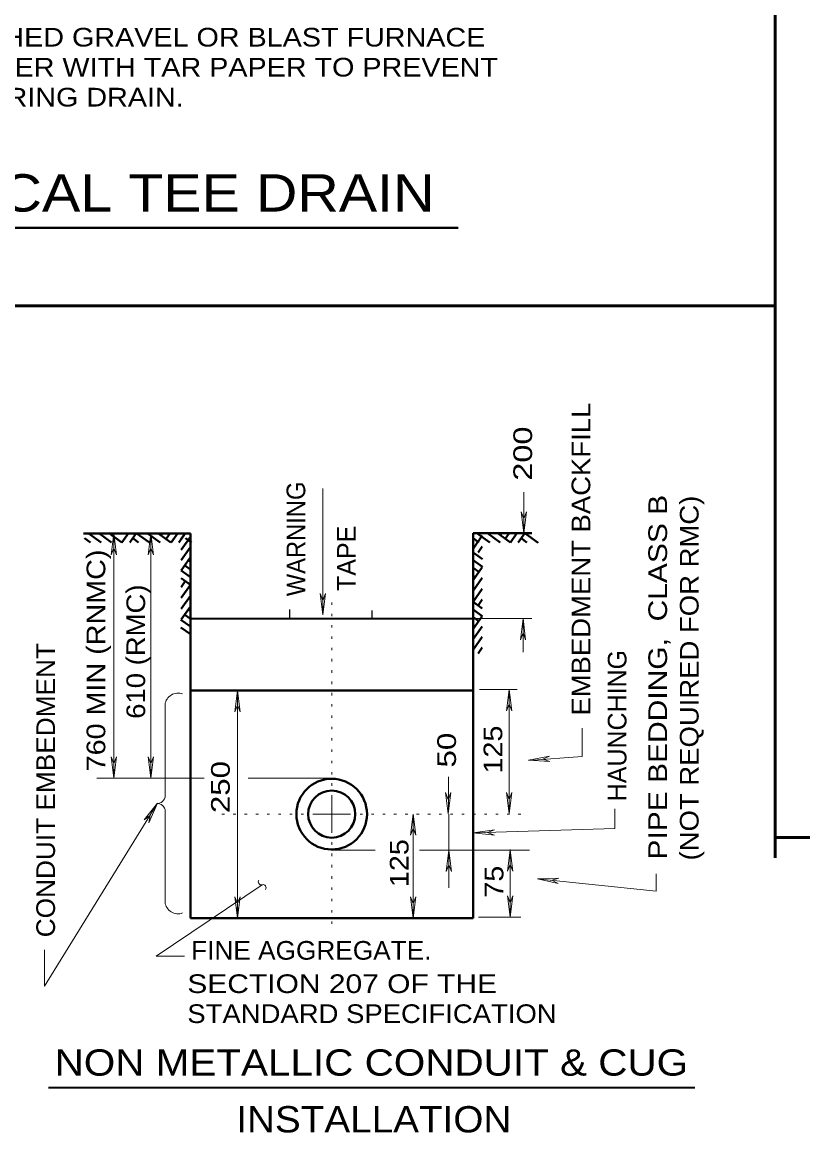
# Model space of a CAD drawing. Extents: x 312583 to 312854, y 144419 to 144597.
# Drawn here: x 312765.96 to 312797.73, y 144444.15 to 144489.34 of the extents above; entities that cross this region are included whole.
import ezdxf
from ezdxf.enums import TextEntityAlignment as Align

# ---------------------------------------------------------------- set-up
doc = ezdxf.new("R2010")
doc.units = 0
doc.header["$LTSCALE"] = 0.3
doc.linetypes.add('DOTTED', pattern=[1.5, 0.3, -1.2])
doc.layers.add('1', color=7, linetype='Continuous', lineweight=40)
doc.layers.add('2', color=7, linetype='Continuous', lineweight=13)

msp = doc.modelspace()

# ---------------------------------------------------------------- linework, layer by layer
at = {"layer": '1', "lineweight": 53}
for p, q in [((312796.6103, 144455.3281), (312796.6103, 144540.9979)), ((312796.6103, 144477.7945), (312742.1369, 144477.7945)), ((312849, 144456.1666), (312796.6103, 144456.1666))]:
    msp.add_line(p, q, dxfattribs=at)
at = {"layer": '1'}
for p, q in [((312772.8133, 144468.5326), (312768.4509, 144468.5326)), ((312769.1793, 144468.1646), (312768.6503, 144468.5479)), ((312769.6009, 144468.1646), (312769.0796, 144468.5402)), ((312770.0226, 144468.1646), (312769.4783, 144468.5556)), ((312769.6623, 144468.5479), (312769.6009, 144468.4636)), ((312770.2909, 144468.5479), (312770.0226, 144468.1646)), ((312770.6053, 144468.5479), (312770.3369, 144468.1646)), ((312771.1419, 144468.1646), (312770.6053, 144468.5479)), ((312771.5789, 144468.1646), (312771.0423, 144468.5479)), ((312772.0159, 144468.1646), (312771.4869, 144468.5479)), ((312771.6709, 144468.5402), (312771.6096, 144468.4559)), ((312771.9853, 144468.5402), (312771.8166, 144468.3102)), ((312772.2996, 144468.5402), (312772.0313, 144468.1646)), ((312772.6139, 144468.5402), (312772.3379, 144468.1646)), ((312772.8133, 144452.8849), (312772.8133, 144468.5326)), ((312784.3133, 144463.6489), (312784.3133, 144468.5479)), ((312784.3133, 144468.5479), (312786.7053, 144468.5479)), ((312784.9956, 144468.1646), (312784.4589, 144468.5479)), ((312785.4173, 144468.1646), (312784.8959, 144468.5402)), ((312785.8313, 144468.1646), (312785.2869, 144468.5556)), ((312785.4709, 144468.5479), (312785.4096, 144468.4636)), ((312785.7853, 144468.5479), (312785.6243, 144468.3179)), ((312786.0996, 144468.5479), (312785.8313, 144468.1646)), ((312786.4139, 144468.5479), (312786.1456, 144468.1646)), ((312786.9583, 144468.1569), (312786.4216, 144468.5402)), ((312768.7423, 144468.1646), (312768.4969, 144468.3409)), ((312770.6973, 144468.1646), (312770.4596, 144468.3409)), ((312772.8516, 144468.1646), (312772.6139, 144468.3409)), ((312784.5509, 144468.1646), (312784.3133, 144468.3409)), ((312786.5059, 144468.1646), (312786.2683, 144468.3409)), ((312778.5556, 144458.5506), (312778.5173, 144458.5506))]:
    msp.add_line(p, q, dxfattribs=at)
at = {"layer": '1', "lineweight": 13}
for p, q in [((312771.7783, 144461.5712), (312771.7783, 144457.9372)), ((312773.3653, 144458.5812), (312768.9953, 144458.5812)), ((312778.5556, 144458.5812), (312775.1593, 144458.5812)), ((312771.7783, 144453.5212), (312771.7783, 144457.1629))]:
    msp.add_line(p, q, dxfattribs=at)
for centre, radius, start, end in [((312772.3085, 144461.4991), 0.5391, 70.18032, 172.10697), ((312771.4615, 144457.8674), 0.3202, 274.55734, 12.2494), ((312771.4615, 144457.2289), 0.3202, 347.7506, 85.44266), ((312772.3085, 144453.5972), 0.5391, 187.89303, 289.81968)]:
    msp.add_arc(centre, radius, start, end, dxfattribs=at)
at = {"layer": '2', "lineweight": 40}
for p, q in [((312759.9676, 144480.9679), (312783.709, 144480.9679)), ((312772.4299, 144468.3102), (312772.5986, 144468.5479)), ((312772.4299, 144467.8656), (312772.8133, 144468.4022)), ((312784.6889, 144468.4482), (312784.3133, 144467.9116)), ((312772.4299, 144467.4439), (312772.7979, 144467.9652)), ((312784.6889, 144468.0036), (312784.5203, 144467.7659)), ((312772.4299, 144467.0299), (312772.8133, 144467.5742)), ((312784.3133, 144467.7659), (312784.6966, 144467.4899)), ((312772.8133, 144466.7616), (312772.4299, 144467.0299)), ((312772.8133, 144467.0682), (312772.5756, 144467.2369)), ((312772.8133, 144467.3826), (312772.7289, 144467.4439)), ((312784.3133, 144467.4516), (312784.6966, 144467.1756)), ((312784.6889, 144467.1679), (312784.3133, 144466.6312)), ((312784.3133, 144467.1372), (312784.5509, 144466.9686)), ((312772.8133, 144466.4472), (312772.4299, 144466.7156)), ((312772.4299, 144466.3476), (312772.5986, 144466.5929)), ((312784.3133, 144466.8229), (312784.3976, 144466.7616)), ((312784.6889, 144466.7309), (312784.3133, 144466.1942)), ((312772.4299, 144465.9106), (312772.8133, 144466.4472)), ((312784.6889, 144466.2862), (312784.3133, 144465.7572)), ((312772.4299, 144465.4736), (312772.8133, 144466.0026)), ((312784.3133, 144465.7572), (312784.6889, 144465.4812)), ((312784.6889, 144465.8492), (312784.5203, 144465.6039)), ((312772.4299, 144465.0289), (312772.8133, 144465.5656)), ((312772.8056, 144465.0596), (312772.5756, 144465.2282)), ((312772.8056, 144465.3739), (312772.7213, 144465.4352)), ((312784.3133, 144465.4429), (312784.6889, 144465.1669)), ((312772.8056, 144464.7529), (312772.4223, 144465.0212)), ((312784.6889, 144465.1669), (312784.3056, 144464.6226)), ((312784.3133, 144465.1286), (312784.5433, 144464.9599)), ((312784.3133, 144464.8142), (312784.3976, 144464.7529)), ((312772.8056, 144464.4386), (312772.4223, 144464.7069)), ((312784.6889, 144464.3312), (312784.3133, 144463.7946)), ((312784.6889, 144464.7529), (312784.3209, 144464.2316)), ((312784.6889, 144463.8942), (312784.5203, 144463.6489)), ((312784.3133, 144463.6489), (312784.3133, 144452.8849)), ((312772.8133, 144462.1386), (312784.3133, 144462.1386)), ((312772.8133, 144452.8849), (312784.3133, 144452.8849))]:
    msp.add_line(p, q, dxfattribs=at)
at = {"layer": '2'}
for p, q in [((312778.1953, 144470.3649), (312778.1953, 144465.2206)), ((312786.3833, 144468.5862), (312786.3833, 144470.2192)), ((312786.2759, 144469.4142), (312786.3833, 144469.1382)), ((312786.3833, 144468.5479), (312786.2759, 144469.4142)), ((312786.4906, 144469.4142), (312786.3833, 144469.1382)), ((312786.3833, 144468.5479), (312786.4906, 144469.4142)), ((312769.6929, 144468.5326), (312769.5856, 144467.6662)), ((312769.6929, 144468.5326), (312769.6929, 144458.5812)), ((312769.6929, 144468.5326), (312769.8003, 144467.6662)), ((312771.2033, 144468.5326), (312771.0959, 144467.6662)), ((312771.2033, 144468.5326), (312771.3106, 144467.6662)), ((312771.2033, 144468.4329), (312771.2033, 144458.5812)), ((312769.5856, 144467.6662), (312769.6929, 144467.9422)), ((312769.8003, 144467.6662), (312769.6929, 144467.9422)), ((312771.0959, 144467.6662), (312771.2033, 144467.9422)), ((312771.3106, 144467.6662), (312771.2033, 144467.9422)), ((312778.0879, 144466.0869), (312778.1953, 144465.8109)), ((312778.1953, 144465.2206), (312778.0879, 144466.0869)), ((312778.3026, 144466.0869), (312778.1953, 144465.8109)), ((312778.1953, 144465.2206), (312778.3026, 144466.0869)), ((312784.3133, 144465.0749), (312786.7053, 144465.0749)), ((312786.3449, 144465.0749), (312786.2376, 144464.2086)), ((312786.3449, 144465.0749), (312786.4523, 144464.2086)), ((312786.3449, 144463.7102), (312786.3449, 144465.0366)), ((312786.2376, 144464.2086), (312786.3449, 144464.4846)), ((312786.4523, 144464.2086), (312786.3449, 144464.4846)), ((312774.7223, 144462.1386), (312774.6149, 144461.2722)), ((312774.7223, 144462.1386), (312774.7223, 144452.8849)), ((312774.7223, 144462.1386), (312774.8296, 144461.2722)), ((312784.5739, 144462.1846), (312786.1099, 144462.1846)), ((312785.781, 144462.1846), (312785.6736, 144461.3182)), ((312785.781, 144462.1156), (312785.781, 144462.1846)), ((312785.781, 144462.1846), (312785.8883, 144461.3182)), ((312785.781, 144462.1846), (312785.781, 144457.1246)), ((312774.6149, 144461.2722), (312774.7223, 144461.5482)), ((312774.8296, 144461.2722), (312774.7223, 144461.5482)), ((312785.6736, 144461.3182), (312785.781, 144461.5942)), ((312785.8883, 144461.3182), (312785.781, 144461.5942)), ((312788.7523, 144460.6129), (312788.7523, 144459.4629)), ((312769.5856, 144459.4476), (312769.6929, 144459.1716)), ((312769.6929, 144458.5812), (312769.5856, 144459.4476)), ((312769.8003, 144459.4476), (312769.6929, 144459.1716)), ((312769.6929, 144458.5812), (312769.8003, 144459.4476)), ((312771.0959, 144459.4476), (312771.2033, 144459.1716)), ((312771.2033, 144458.5812), (312771.0959, 144459.4476)), ((312771.3106, 144459.4476), (312771.2033, 144459.1716)), ((312771.2033, 144458.5812), (312771.3106, 144459.4476)), ((312786.5673, 144459.3096), (312787.4183, 144459.4706)), ((312788.7523, 144459.4629), (312786.5673, 144459.3019)), ((312787.4183, 144459.4706), (312787.1576, 144459.3479)), ((312787.4413, 144459.2559), (312787.1576, 144459.3479)), ((312786.5673, 144459.3096), (312787.4413, 144459.2559)), ((312783.3089, 144458.6349), (312783.3089, 144457.1936)), ((312783.1939, 144457.9909), (312783.3013, 144457.7149)), ((312783.3013, 144457.1246), (312783.1939, 144457.9909)), ((312783.4086, 144457.9909), (312783.3013, 144457.7149)), ((312783.3013, 144457.1246), (312783.4086, 144457.9909)), ((312785.6736, 144457.9909), (312785.781, 144457.7149)), ((312785.781, 144457.1246), (312785.6736, 144457.9909)), ((312785.8883, 144457.9909), (312785.781, 144457.7149)), ((312785.781, 144457.1246), (312785.8883, 144457.9909)), ((312771.4716, 144457.5616), (312770.9273, 144456.8792)), ((312771.4716, 144457.5616), (312771.1113, 144456.7642)), ((312778.5633, 144457.1169), (312778.5633, 144457.8836)), ((312778.5633, 144457.1169), (312777.7966, 144457.1169)), ((312778.5633, 144457.1169), (312779.3299, 144457.1169)), ((312778.5633, 144457.1169), (312778.5633, 144456.3502)), ((312781.8753, 144457.1169), (312781.7679, 144456.2506)), ((312781.8753, 144457.1169), (312781.8753, 144452.8849)), ((312781.8753, 144457.1169), (312781.9826, 144456.2506)), ((312783.3243, 144457.1092), (312783.3243, 144455.6602)), ((312790.0786, 144457.3239), (312790.0786, 144456.5342)), ((312770.9273, 144456.8792), (312771.1649, 144457.0556)), ((312771.1113, 144456.7642), (312771.1649, 144457.0556)), ((312781.7679, 144456.2506), (312781.8753, 144456.5266)), ((312781.9826, 144456.2506), (312781.8753, 144456.5266)), ((312784.3133, 144456.3579), (312785.1796, 144456.4729)), ((312784.3133, 144456.3579), (312785.1796, 144456.2582)), ((312790.0786, 144456.5342), (312784.3593, 144456.3579)), ((312785.1796, 144456.4729), (312784.9036, 144456.3656)), ((312785.1796, 144456.2582), (312784.9036, 144456.3656)), ((312778.5249, 144455.6526), (312780.3343, 144455.6526)), ((312782.1359, 144455.6526), (312786.606, 144455.6526)), ((312783.3243, 144455.6449), (312783.2169, 144454.7786)), ((312783.3243, 144455.6449), (312783.4316, 144454.7786)), ((312783.3243, 144455.5529), (312783.3243, 144454.1116)), ((312785.8164, 144455.6526), (312785.709, 144454.7862)), ((312785.8164, 144455.6679), (312785.8164, 144452.9156)), ((312785.8164, 144455.6526), (312785.9237, 144454.7862)), ((312783.2169, 144454.7786), (312783.3243, 144455.0546)), ((312783.4316, 144454.7786), (312783.3243, 144455.0546)), ((312785.709, 144454.7862), (312785.8164, 144455.0622)), ((312785.9237, 144454.7862), (312785.8164, 144455.0622)), ((312786.9283, 144454.4865), (312787.8023, 144454.5095)), ((312791.7653, 144453.9812), (312786.9283, 144454.4865)), ((312786.9283, 144454.4865), (312787.7793, 144454.2948)), ((312787.8023, 144454.5095), (312787.5186, 144454.4251)), ((312787.7793, 144454.2948), (312787.5186, 144454.4251)), ((312791.7653, 144454.6866), (312791.7653, 144453.9812)), ((312771.4179, 144451.3286), (312775.7266, 144454.2419)), ((312774.6149, 144453.7512), (312774.7223, 144453.4752)), ((312774.7223, 144452.8849), (312774.6149, 144453.7512)), ((312774.8296, 144453.7512), (312774.7223, 144453.4752)), ((312774.7223, 144452.8849), (312774.8296, 144453.7512)), ((312781.7679, 144453.7512), (312781.8753, 144453.4752)), ((312781.8753, 144452.8849), (312781.7679, 144453.7512)), ((312781.9826, 144453.7512), (312781.8753, 144453.4752)), ((312781.8753, 144452.8849), (312781.9826, 144453.7512)), ((312785.709, 144453.7819), (312785.8164, 144453.5059)), ((312785.8164, 144452.9156), (312785.709, 144453.7819)), ((312785.9237, 144453.7819), (312785.8164, 144453.5059)), ((312785.8164, 144452.9156), (312785.9237, 144453.7819)), ((312774.6686, 144453.3219), (312774.7223, 144453.1839)), ((312774.7223, 144452.8849), (312774.6686, 144453.3219)), ((312774.7759, 144453.3219), (312774.7223, 144453.1839)), ((312774.7223, 144452.8849), (312774.7759, 144453.3219)), ((312784.5356, 144452.9156), (312786.2516, 144452.9156)), ((312771.4179, 144451.3286), (312772.5679, 144451.3286))]:
    msp.add_line(p, q, dxfattribs=at)
at = {"layer": '2', "linetype": 'DOTTED'}
for p, q in [((312778.5633, 144458.2669), (312778.5633, 144465.9336)), ((312777.4133, 144457.1169), (312774.0783, 144457.1169)), ((312779.7133, 144457.1169), (312786.3934, 144457.1169)), ((312778.5633, 144455.9669), (312778.5633, 144452.4096))]:
    msp.add_line(p, q, dxfattribs=at)
at = {"layer": '2', "lineweight": 25}
for p, q in [((312776.8613, 144465.0749), (312776.8613, 144465.4429)), ((312780.2039, 144465.0442), (312780.2039, 144465.4046))]:
    msp.add_line(p, q, dxfattribs=at)
at = {"layer": '2', "lineweight": 35}
for p, q in [((312772.8133, 144465.0749), (312784.3133, 144465.0749)), ((312767.0348, 144445.9915), (312793.3314, 144445.9915))]:
    msp.add_line(p, q, dxfattribs=at)
at = {"layer": '2'}
msp.add_lwpolyline([(312766.8716, 144451.5969), (312766.8716, 144450.1172), (312771.4716, 144457.5616)], dxfattribs=at)
at = {"layer": '2', "lineweight": 40}
for radius in [1.4375, 0.9583]:
    msp.add_circle((312778.5594, 144457.1131), radius, dxfattribs=at)
at = {"layer": '2'}
for centre, start, end in [((312775.6895, 144454.3532), 139.00623, 289.00623), ((312775.7675, 144454.1267), 319.00623, 109.00623)]:
    msp.add_arc(centre, 0.1198, start, end, dxfattribs=at)

# ---------------------------------------------------------------- texts
for s, width, p in [('BROKEN STONE,  WASHED GRAVEL OR BLAST FURNACE', 1.15, (312752.2745, 144488.3489)), ('SLAG FOR DRAIN.  COVER WITH TAR PAPER TO PREVENT', 1.15, (312752.2745, 144487.1289)), ('BACK FILL FROM ENTERING DRAIN.', 1.15, (312752.2745, 144485.9089)), ('FINE AGGREGATE.', 1.05, (312772.8363, 144451.1896)), ('SECTION 207 OF THE', 1.2, (312772.6829, 144449.8326)), ('STANDARD SPECIFICATION', 1.1, (312772.6829, 144448.6126))]:
    msp.add_text(s, height=0.76, dxfattribs=dict(at, width=width)).set_placement(p)
for s, height, width, p in [('TYPICAL TEE DRAIN', 1.52, 1.15, (312771.3153, 144481.633)), ('NON METALLIC CONDUIT & CUG', 1.07, 1.15, (312780.1719, 144446.4706)), ('INSTALLATION', 1.07, 1.1, (312780.2723, 144444.1611))]:
    msp.add_text(s, height=height, dxfattribs=dict(at, width=width)).set_placement(p, align=Align.CENTER)
for s, width, p in [('EMBEDMENT BACKFILL', 1.1, (312789.0822, 144461.1218)), ('200 ', 1.3, (312786.7122, 144470.6812)), ('WARNING', 0.95, (312777.4833, 144465.9796)), ('PIPE BEDDING,  CLASS B', 1.2, (312792.2064, 144455.2644)), ('(NOT REQUIRED FOR RMC)', 1.1, (312793.4906, 144455.229)), ('760 MIN (RNMC)', 1.15, (312769.3444, 144458.8548)), ('610 (RMC)', 1.1, (312770.9649, 144460.9915)), ('CONDUIT EMBEDMENT', 1.05, (312767.2974, 144452.101)), ('50 ', 1.25, (312783.616, 144459.0115)), ('125 ', 1.15, (312785.4999, 144458.7654)), ('250 ', 1.25, (312774.4102, 144457.1544)), ('125 ', 1.15, (312781.6846, 144454.1422)), ('75 ', 1.15, (312785.5466, 144453.7134))]:
    msp.add_text(s, height=0.76, rotation=90, dxfattribs=dict(at, width=width)).set_placement(p)
for s, p in [('TAPE', (312779.5379, 144466.1942)), ('HAUNCHING', (312790.5551, 144457.6382))]:
    msp.add_text(s, height=0.76, rotation=90, dxfattribs=at).set_placement(p)

doc.saveas('drawing.dxf')
